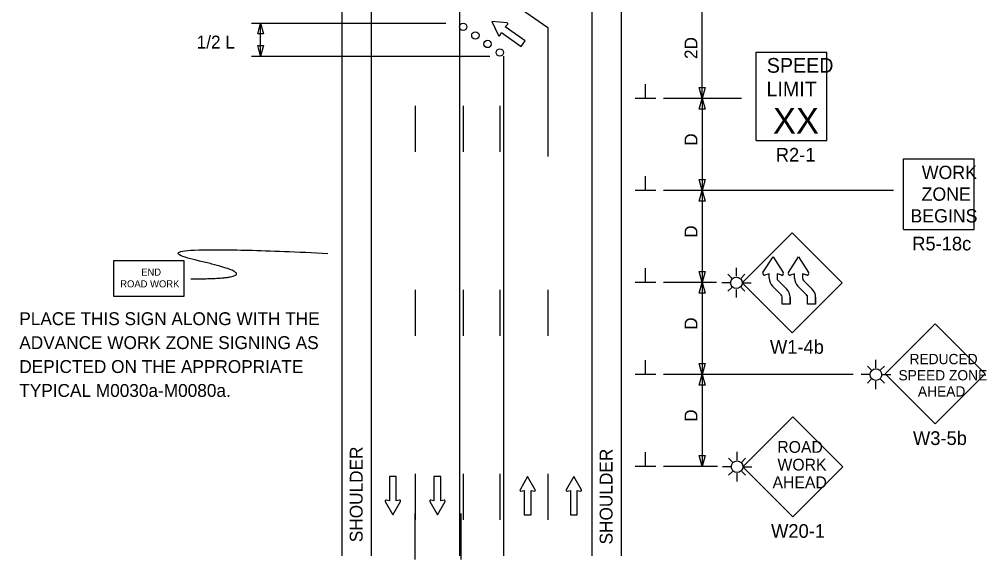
# Model space of a CAD drawing. Extents: x 16577 to 18475, y 5712 to 6919.
# Drawn here: x 16731 to 17257, y 6137 to 6431 of the extents above; entities that cross this region are included whole.
import ezdxf

# ---------------------------------------------------------------- set-up
doc = ezdxf.new("R2010")
doc.units = 0
for name, color, linetype in [('ALI_LEGAL_EX', 7, 'Continuous'), ('MT_SCRATCH_LEVEL_E', 7, 'Continuous'), ('PAVT_EDGE_EX', 7, 'Continuous'), ('TRAFFIC_SIGNS_PR', 7, 'Continuous'), ('TYPICAL_TEXT_DIMEN_PR', 7, 'Continuous')]:
    doc.layers.add(name, color=color, linetype=linetype)

msp = doc.modelspace()

# ---------------------------------------------------------------- linework, layer by layer
at = {"layer": 'ALI_LEGAL_EX'}
for points in [[(16946.75, 6383.94), (16946.75, 6358.94)], [(16972.75, 6383.94), (16972.75, 6358.94)], [(16992.75, 6383.94), (16992.75, 6358.94)], [(17018.75, 6383.94), (17018.75, 6358.94)], [(16946.75, 6283.94), (16946.75, 6258.94)], [(16972.75, 6283.94), (16972.75, 6258.94)], [(16992.75, 6283.94), (16992.75, 6258.94)], [(17018.75, 6283.94), (17018.75, 6258.94)], [(16946.75, 6183.94), (16946.75, 6158.94)], [(16946.75, 6183.94), (16946.75, 6158.94)], [(16972.75, 6183.94), (16972.75, 6158.94)], [(16992.75, 6183.94), (16992.75, 6158.94)], [(17018.75, 6183.94), (17018.75, 6158.94)]]:
    msp.add_lwpolyline(points, dxfattribs=at)
at = {"layer": 'MT_SCRATCH_LEVEL_E'}
for p, q in [((16988.37, 6429.76), (16991.95, 6422.25)), ((16996.68, 6429.02), (16988.37, 6429.76)), ((16988.37, 6429.76), (16991.95, 6422.25)), ((16996.68, 6429.02), (16988.37, 6429.76)), ((16992.79, 6422.25), (16993.55, 6423.89)), ((16992.79, 6422.25), (16993.55, 6423.89)), ((16993.55, 6423.89), (17004.42, 6416.3)), ((16993.55, 6423.89), (17004.42, 6416.3)), ((16995.69, 6426.96), (16996.97, 6428.23)), ((16995.69, 6426.96), (16996.97, 6428.23)), ((17006.56, 6419.36), (16995.69, 6426.96)), ((17006.56, 6419.36), (16995.69, 6426.96)), ((17004.42, 6416.3), (17006.56, 6419.36)), ((17004.42, 6416.3), (17006.56, 6419.36)), ((16936.42, 6182.61), (16932.68, 6182.61)), ((16932.68, 6182.61), (16932.68, 6169.35)), ((16936.42, 6182.61), (16932.68, 6182.61)), ((16932.68, 6182.61), (16932.68, 6169.35)), ((16936.42, 6169.35), (16936.42, 6182.61)), ((16936.42, 6169.35), (16936.42, 6182.61)), ((16960.67, 6182.61), (16956.93, 6182.61)), ((16956.93, 6182.61), (16956.93, 6169.35)), ((16960.67, 6182.61), (16956.93, 6182.61)), ((16956.93, 6182.61), (16956.93, 6169.35)), ((16960.67, 6169.35), (16960.67, 6182.61)), ((16960.67, 6169.35), (16960.67, 6182.61)), ((17007.86, 6182.61), (17003.75, 6175.37)), ((17007.86, 6182.61), (17003.75, 6175.37)), ((17012.01, 6175.37), (17007.86, 6182.61)), ((17012.01, 6175.37), (17007.86, 6182.61)), ((17032.95, 6182.61), (17028.84, 6175.37)), ((17032.95, 6182.61), (17028.84, 6175.37)), ((17037.1, 6175.37), (17032.95, 6182.61)), ((17037.1, 6175.37), (17032.95, 6182.61)), ((17004.24, 6174.68), (17006.01, 6175)), ((17004.24, 6174.68), (17006.01, 6175)), ((17006.01, 6175), (17006.01, 6161.74)), ((17006.01, 6175), (17006.01, 6161.74)), ((17009.75, 6161.74), (17009.75, 6175)), ((17009.75, 6175), (17011.53, 6174.68)), ((17009.75, 6161.74), (17009.75, 6175)), ((17009.75, 6175), (17011.53, 6174.68)), ((17029.32, 6174.68), (17031.1, 6175)), ((17029.32, 6174.68), (17031.1, 6175)), ((17031.1, 6175), (17031.1, 6161.74)), ((17031.1, 6175), (17031.1, 6161.74)), ((17034.84, 6161.74), (17034.84, 6175)), ((17034.84, 6175), (17036.62, 6174.68)), ((17034.84, 6161.74), (17034.84, 6175)), ((17034.84, 6175), (17036.62, 6174.68)), ((16930.42, 6168.98), (16934.57, 6161.74)), ((16930.42, 6168.98), (16934.57, 6161.74)), ((16932.68, 6169.35), (16930.9, 6169.67)), ((16932.68, 6169.35), (16930.9, 6169.67)), ((16934.57, 6161.74), (16938.68, 6168.98)), ((16934.57, 6161.74), (16938.68, 6168.98)), ((16938.2, 6169.67), (16936.42, 6169.35)), ((16938.2, 6169.67), (16936.42, 6169.35)), ((16954.68, 6168.98), (16958.82, 6161.74)), ((16954.68, 6168.98), (16958.82, 6161.74)), ((16956.93, 6169.35), (16955.15, 6169.67)), ((16956.93, 6169.35), (16955.15, 6169.67)), ((16958.82, 6161.74), (16962.93, 6168.98)), ((16958.82, 6161.74), (16962.93, 6168.98)), ((16962.45, 6169.67), (16960.67, 6169.35)), ((16962.45, 6169.67), (16960.67, 6169.35)), ((17006.01, 6161.74), (17009.75, 6161.74)), ((17006.01, 6161.74), (17009.75, 6161.74)), ((17031.1, 6161.74), (17034.84, 6161.74)), ((17031.1, 6161.74), (17034.84, 6161.74))]:
    msp.add_line(p, q, dxfattribs=at)
for centre, start, end in [((16996.63, 6428.55), 315.105, 84.8419), ((16996.63, 6428.55), 315.105, 84.8419), ((16992.37, 6422.45), 205.4936, 335.0326), ((16992.37, 6422.45), 205.4936, 335.0326), ((17004.16, 6175.14), 150.4248, 279.9638), ((17004.16, 6175.14), 150.4248, 279.9638), ((17011.6, 6175.14), 260.0362, 29.7731), ((17011.6, 6175.14), 260.0362, 29.7731), ((17029.25, 6175.14), 150.4248, 279.9638), ((17029.25, 6175.14), 150.4248, 279.9638), ((17036.69, 6175.14), 260.0362, 29.7731), ((17036.69, 6175.14), 260.0362, 29.7731), ((16930.83, 6169.21), 80.0362, 209.7731), ((16930.83, 6169.21), 80.0362, 209.7731), ((16938.27, 6169.21), 330.4248, 99.9638), ((16938.27, 6169.21), 330.4248, 99.9638), ((16955.09, 6169.21), 80.0362, 209.7731), ((16955.09, 6169.21), 80.0362, 209.7731), ((16962.53, 6169.21), 330.4248, 99.9638), ((16962.53, 6169.21), 330.4248, 99.9638)]:
    msp.add_arc(centre, 0.463, start, end, dxfattribs=at)
at = {"layer": 'PAVT_EDGE_EX'}
for p, q in [((16906.75, 6901.43), (16906.75, 6139.45)), ((16922.75, 6901.43), (16922.75, 6139.45)), ((16970.75, 6901.43), (16970.75, 6139.45)), ((17042.75, 6901.43), (17042.75, 6139.45)), ((17058.75, 6901.43), (17058.75, 6139.45)), ((16994.75, 6443.28), (17018.75, 6426.52)), ((17018.75, 6426.52), (17018.75, 6356.47)), ((16994.75, 6410.96), (16994.75, 6139.45))]:
    msp.add_line(p, q, dxfattribs=at)
for points in [[(16946.75, 6137.4), (16946.75, 6162.4)], [(16971.75, 6137.4), (16971.75, 6162.4)]]:
    msp.add_lwpolyline(points, dxfattribs=at)
at = {"layer": 'TRAFFIC_SIGNS_PR'}
for p, q in [((17132.15, 6413.12), (17170.55, 6413.12)), ((17132.15, 6365.12), (17132.15, 6413.12)), ((17170.55, 6365.12), (17170.55, 6413.12)), ((17132.15, 6365.12), (17170.55, 6365.12)), ((17212.21, 6316.86), (17212.21, 6355.26)), ((17212.21, 6355.26), (17250.61, 6355.26)), ((17250.61, 6316.86), (17250.61, 6355.26)), ((17124.55, 6287.83), (17151.7, 6314.99)), ((17151.7, 6314.99), (17178.85, 6287.83)), ((17212.21, 6316.86), (17250.61, 6316.86)), ((17118.88, 6290.35), (17116.77, 6292.45)), ((17121.39, 6291.39), (17121.39, 6295.89)), ((17123.91, 6290.35), (17126.02, 6292.45)), ((17118.24, 6287.83), (17113.4, 6287.83)), ((17124.55, 6287.83), (17129.43, 6287.83)), ((17151.7, 6260.68), (17124.55, 6287.83)), ((17148.77, 6284.37), (17144.06, 6289.08)), ((17144.06, 6289.08), (17148.77, 6284.37)), ((17178.85, 6287.83), (17151.7, 6260.68)), ((17162.57, 6284.37), (17157.85, 6289.08)), ((17157.85, 6289.08), (17162.57, 6284.37)), ((17118.88, 6285.32), (17116.77, 6283.21)), ((17121.39, 6279.87), (17121.39, 6284.28)), ((17123.91, 6285.32), (17126.01, 6283.21)), ((17145.72, 6281.31), (17141.01, 6286.03)), ((17145.72, 6281.31), (17141.01, 6286.03)), ((17159.52, 6281.31), (17154.8, 6286.03)), ((17159.51, 6281.31), (17154.8, 6286.03)), ((17146.32, 6276.25), (17146.32, 6279.95)), ((17150.64, 6276.25), (17146.32, 6276.25)), ((17150.64, 6276.25), (17150.64, 6279.95)), ((17160.12, 6276.25), (17160.12, 6279.95)), ((17164.43, 6276.25), (17160.12, 6276.25)), ((17164.43, 6276.25), (17164.43, 6279.95)), ((17229.49, 6265.45), (17202.34, 6238.29)), ((17256.64, 6238.29), (17229.49, 6265.45)), ((17197.26, 6241.51), (17197.26, 6246.01)), ((17194.75, 6240.47), (17192.64, 6242.57)), ((17199.77, 6240.47), (17201.88, 6242.57)), ((17194.11, 6237.95), (17189.27, 6237.95)), ((17194.75, 6235.44), (17192.64, 6233.33)), ((17197.26, 6229.99), (17197.26, 6234.4)), ((17199.77, 6235.44), (17201.88, 6233.33)), ((17200.41, 6237.95), (17205.3, 6237.95)), ((17202.34, 6238.29), (17229.49, 6211.14)), ((17229.49, 6211.14), (17256.64, 6238.29)), ((17152.1, 6215.08), (17124.91, 6187.89)), ((17179.28, 6187.89), (17152.1, 6215.08)), ((17119.24, 6190.4), (17117.13, 6192.51)), ((17121.75, 6191.45), (17121.75, 6195.95)), ((17124.27, 6190.4), (17126.38, 6192.51)), ((17118.6, 6187.89), (17113.76, 6187.89)), ((17124.91, 6187.89), (17152.1, 6160.7)), ((17124.91, 6187.89), (17129.79, 6187.89)), ((17152.1, 6160.7), (17179.28, 6187.89)), ((17119.24, 6185.38), (17117.13, 6183.27)), ((17121.75, 6179.93), (17121.75, 6184.34)), ((17124.27, 6185.38), (17126.37, 6183.27))]:
    msp.add_line(p, q, dxfattribs=at)
msp.add_lwpolyline([(16782.69, 6280.6), (16821.09, 6280.6), (16821.09, 6299.8), (16782.69, 6299.8)], close=True, dxfattribs=at)
for points in [[(17135.85, 6293.36), (17141.33, 6301.97), (17146.81, 6293.36)], [(17135.85, 6293.36), (17141.33, 6301.97), (17146.81, 6293.36)], [(17149.65, 6293.36), (17155.13, 6301.97), (17160.61, 6293.36)], [(17149.65, 6293.36), (17155.13, 6301.97), (17160.61, 6293.36)], [(17139.18, 6290.34), (17139.18, 6292.71), (17136.81, 6292.06)], [(17139.18, 6290.34), (17139.18, 6292.71), (17136.81, 6292.06)], [(17145.85, 6292.06), (17143.49, 6292.71), (17143.5, 6290.41)], [(17145.85, 6292.06), (17145.02, 6292.29), (17143.49, 6292.71), (17143.5, 6290.41)], [(17152.98, 6290.34), (17152.97, 6292.71), (17150.61, 6292.06)], [(17152.98, 6290.34), (17152.97, 6292.71), (17150.61, 6292.06)], [(17159.65, 6292.06), (17157.29, 6292.71), (17157.29, 6290.41)], [(17159.65, 6292.06), (17158.82, 6292.29), (17157.29, 6292.71), (17157.29, 6290.41)], [(17150.64, 6279.95), (17150.64, 6276.25), (17146.32, 6276.25), (17146.32, 6279.95)], [(17164.44, 6279.95), (17164.43, 6276.25), (17160.12, 6276.25), (17160.12, 6279.95)]]:
    msp.add_lwpolyline(points, dxfattribs=at)
for centre, radius in [((16972.75, 6426.93), 2), ((16972.75, 6426.93), 2), ((16979.42, 6422.27), 2), ((16986.08, 6417.62), 2), ((16992.75, 6412.96), 2), ((17121.39, 6287.83), 3.15), ((17197.26, 6237.95), 3.15), ((17121.75, 6187.89), 3.15)]:
    msp.add_circle(centre, radius, dxfattribs=at)
for centre, radius, start, end in [((17136.58, 6292.89), 0.866, 147.7292, 285.3172), ((17136.58, 6292.89), 0.866, 147.7196, 285.3201), ((17126.74, 6299.15), 10.8, 327.5335, 327.5431), ((17139.67, 6281.64), 10.8, 105.3192, 105.32), ((17146.08, 6292.89), 0.864, 254.6014, 32.4796), ((17146.08, 6292.89), 0.866, 254.6148, 32.4712), ((17150.38, 6292.89), 0.866, 147.7292, 285.3172), ((17150.38, 6292.89), 0.866, 147.7196, 285.3201), ((17140.54, 6299.15), 10.8, 327.5335, 327.5431), ((17153.46, 6281.64), 10.8, 105.3192, 105.32), ((17159.88, 6292.89), 0.864, 254.6014, 32.4796), ((17159.88, 6292.89), 0.866, 254.6148, 32.4712), ((17145.35, 6290.41), 6.17, 180.6181, 225.7875), ((17145.35, 6290.41), 6.17, 180.6245, 225.2313), ((17145.35, 6290.41), 1.85, 180, 225.7875), ((17145.35, 6290.41), 1.85, 179.8762, 225.7877), ((17159.14, 6290.41), 6.17, 180.6181, 225.7875), ((17159.14, 6290.41), 6.17, 180.6245, 225.2313), ((17159.14, 6290.41), 1.85, 180, 225.7875), ((17159.14, 6290.41), 1.85, 179.8762, 225.7877), ((17144.47, 6279.95), 1.85, 0, 47.628), ((17144.47, 6279.95), 1.85, 0, 45.7875), ((17144.47, 6279.95), 6.17, 0, 45.7875), ((17144.47, 6279.95), 6.17, 0, 45.7875), ((17144.47, 6279.95), 6.17, 0, 45.7883), ((17158.27, 6279.95), 1.85, 0, 47.628), ((17158.27, 6279.95), 1.85, 0, 45.7875), ((17158.27, 6279.95), 6.17, 0, 45.7875), ((17158.27, 6279.95), 6.17, 0, 45.7875), ((17158.27, 6279.95), 6.17, 0, 45.7883)]:
    msp.add_arc(centre, radius, start, end, dxfattribs=at)
msp.add_open_spline([(16824.68, 6289.98), (16871.92, 6289.98), (16786.89, 6309.33), (16899.19, 6303.84)], degree=2, dxfattribs=at)
at = {"layer": 'TYPICAL_TEXT_DIMEN_PR'}
for p, q in [((17102.75, 6388.07), (17102.75, 6438.07)), ((16857.65, 6428.93), (16963.28, 6428.93)), ((16861.08, 6423.07), (16862.65, 6428.93)), ((16862.65, 6410.96), (16862.65, 6428.93)), ((16862.65, 6428.93), (16864.22, 6423.07)), ((16862.65, 6423.07), (16861.08, 6423.07)), ((16864.22, 6423.07), (16862.65, 6423.07)), ((16862.65, 6410.96), (16861.08, 6416.82)), ((16861.08, 6416.82), (16862.65, 6416.82)), ((16862.65, 6416.82), (16864.22, 6416.82)), ((16864.22, 6416.82), (16862.65, 6410.96)), ((16857.65, 6410.96), (16987.28, 6410.96)), ((17071.87, 6388.07), (17071.87, 6395.86)), ((17102.75, 6388.07), (17101.18, 6393.94)), ((17101.18, 6393.94), (17102.75, 6393.94)), ((17102.75, 6393.94), (17104.32, 6393.94)), ((17104.32, 6393.94), (17102.75, 6388.07)), ((17077.5, 6388.07), (17066.25, 6388.07)), ((17124.1, 6388.07), (17081.75, 6388.07)), ((17101.18, 6382.21), (17102.75, 6388.07)), ((17102.75, 6388.07), (17104.32, 6382.21)), ((17102.75, 6388.07), (17102.75, 6338.07)), ((17102.75, 6382.21), (17101.18, 6382.21)), ((17104.32, 6382.21), (17102.75, 6382.21)), ((17071.87, 6338.07), (17071.87, 6345.86)), ((17102.75, 6338.07), (17101.18, 6343.94)), ((17101.18, 6343.94), (17102.75, 6343.94)), ((17102.75, 6343.94), (17104.32, 6343.94)), ((17104.32, 6343.94), (17102.75, 6338.07)), ((17077.5, 6338.07), (17066.25, 6338.07)), ((17206.83, 6338.07), (17081.75, 6338.07)), ((17101.18, 6332.21), (17102.75, 6338.07)), ((17102.75, 6338.07), (17104.32, 6332.21)), ((17102.75, 6338.07), (17102.75, 6288.07)), ((17102.75, 6332.21), (17101.18, 6332.21)), ((17104.32, 6332.21), (17102.75, 6332.21)), ((17071.87, 6288.07), (17071.87, 6295.86)), ((17102.75, 6288.07), (17101.18, 6293.94)), ((17101.18, 6293.94), (17102.75, 6293.94)), ((17102.75, 6293.94), (17104.32, 6293.94)), ((17104.32, 6293.94), (17102.75, 6288.07)), ((17077.5, 6288.07), (17066.25, 6288.07)), ((17110.51, 6288.07), (17081.75, 6288.07)), ((17101.18, 6282.21), (17102.75, 6288.07)), ((17102.75, 6288.07), (17104.32, 6282.21)), ((17102.75, 6288.07), (17102.75, 6238.07)), ((17102.75, 6282.21), (17101.18, 6282.21)), ((17104.32, 6282.21), (17102.75, 6282.21)), ((17071.87, 6238.07), (17071.87, 6245.86)), ((17102.75, 6238.07), (17101.18, 6243.94)), ((17101.18, 6243.94), (17102.75, 6243.94)), ((17102.75, 6243.94), (17104.32, 6243.94)), ((17104.32, 6243.94), (17102.75, 6238.07)), ((17077.5, 6238.07), (17066.25, 6238.07)), ((17184.84, 6238.07), (17081.75, 6238.07)), ((17101.18, 6232.21), (17102.75, 6238.07)), ((17102.75, 6238.07), (17102.75, 6188.07)), ((17102.75, 6238.07), (17104.32, 6232.21)), ((17102.75, 6232.21), (17101.18, 6232.21)), ((17104.32, 6232.21), (17102.75, 6232.21)), ((17071.87, 6188.07), (17071.87, 6195.86)), ((17102.75, 6188.07), (17101.18, 6193.94)), ((17101.18, 6193.94), (17102.75, 6193.94)), ((17102.75, 6193.94), (17104.32, 6193.94)), ((17104.32, 6193.94), (17102.75, 6188.07)), ((17077.5, 6188.07), (17066.25, 6188.07)), ((17111.1, 6188.07), (17081.75, 6188.07))]:
    msp.add_line(p, q, dxfattribs=at)

# ---------------------------------------------------------------- texts
at = {"layer": 'TRAFFIC_SIGNS_PR'}
for s, height, p in [('SPEED', 8, (17137.91, 6401.98)), ('LIMIT', 8, (17137.75, 6389.18)), ('XX', 14.031, (17141.26, 6368.88)), ('R2-1', 7.44, (17142.82, 6353.68)), ('WORK', 7.217, (17222.21, 6344.23)), ('ZONE', 7.217, (17222.09, 6332.42)), ('BEGINS', 7.217, (17216.02, 6320.61)), ('R5-18c', 7.44, (17217.02, 6305.42)), ('END', 3.831, (16797.69, 6291.73)), ('ROAD WORK', 3.831, (16786.3, 6285.35)), ('PLACE THIS SIGN ALONG WITH THE', 7, (16731.41, 6264.82)), ('ADVANCE WORK ZONE SIGNING AS', 7, (16731.41, 6251.82)), ('W1-4b', 7.44, (17139.65, 6249.24)), ('DEPICTED ON THE APPROPRIATE', 7, (16731.41, 6238.82)), ('REDUCED', 5.6, (17215.55, 6243.6)), ('SPEED ZONE', 5.6, (17209.54, 6234.8)), ('TYPICAL M0030a-M0080a.', 7, (16731.41, 6225.82)), ('AHEAD', 5.6, (17220.1, 6226)), ('W3-5b', 7.44, (17217.44, 6199.7)), ('ROAD', 6.408, (17143.63, 6195.44)), ('WORK', 6.408, (17143.73, 6185.82)), ('AHEAD', 6.408, (17141.04, 6176.21)), ('W20-1', 7.449, (17140.25, 6149.25))]:
    msp.add_text(s, height=height, dxfattribs=at).set_placement(p)
at = {"layer": 'TYPICAL_TEXT_DIMEN_PR'}
msp.add_text('1/2 L', height=7, dxfattribs=at).set_placement((16827.85, 6415.15))
for s, p in [('2D', (17100.19, 6409.42)), ('D', (17100.19, 6362.29)), ('D', (17100.19, 6312.29)), ('D', (17100.19, 6262.29)), ('D', (17100.19, 6212.29)), ('SHOULDER', (16918.13, 6146.85)), ('SHOULDER', (17054.03, 6145.66))]:
    msp.add_text(s, height=7, rotation=90, dxfattribs=at).set_placement(p)

doc.saveas('drawing.dxf')
